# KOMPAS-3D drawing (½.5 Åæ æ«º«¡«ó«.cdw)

Views: Вид 1
Referenced files: План ПС Сазоново.cdw
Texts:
  Ирина
  Текст на чертеже
  Размерные надписи
  Шероховатость
  Линия-выноска #1
  Линия-выноска #2
  Линия-выноска #3
  Отклонения формы и база
  Заголовок таблицы
  Ячейка таблицы
  Стрелка вида
  Обозначение изменения
  Фигурная скобка
  Номер узла
  Марка координационной оси
  VRCB
  Выносная надпись
  Обозначение узла
  Марка/позиционное обозначение с линией-выноской
  Марка/позиционное обозначение на линии
  Марка/позиционное обозначение без линии-выноски
  Normal
  Лит-Масса-Масштаб
  Материал-Предприятие
  Title Specification
  Body Specification ( left align )
  Body Specificaton ( centered )
  Без имени
  heading 1
  Знак Знак Знак Знак Знак Знак
  Verdana
  Body Text
  MS Sans Serif
  Txt
  Simplex
  TXT
  Обычный
  Термин
  Список определений
  Адрес
  Цитаты
  Форматированный
  Courier New
  Z-конец формы
  Z-начало формы
  Additional DXF text style 0
  Абзац Знак
  Body Text 3
  Title
  ТекстШаг1
  Шрифт 2.5
  Заголовки
  txt
  heading 2
  AGOpus
  footer
  Денис
  RUSTXT
  Обычный (веб)
  ООббыыччнныыйй
  Definition Term
  Definition List
  Address
  Blockquote
  Preformatted
  z-Bottom of Form
  z-Top of Form
  header
  NormalParagraphStyle
  ссылки
  Подпись в квадратике
  табл
  цепи
  Маркировка
  клеммы, контакты
  тексты табл
  Тексты. 3,2
  ЗОНА_привяз
  текст переноса
  ТТееррммиинн
  ССппииссоокк ооппррееддееллеенниийй
  ААддрреесс
  ЦЦииттааттыы
  ФФооррммааттиирроовваанннныыйй
  Z-ккооннеецц ффооррммыы
  Z-ннааччааллоо ффооррммыы
  GOST 2.304 type A
  rustxt
  heading 8
  heading 3
  heading 6
  heading 7
  russ
  heading 4
  heading 5
  heading 9
  HeliosLight
  Pa3
  Pa1
  Три с половиной
  style2
  Table Contents
  Table Heading
  ГОСТ_МНЕ
  ESK - Обозначение
  маркировка
  ISOCP
  ROMANS
  SIMPLEX
  Текст 3,5
  Tahoma
  текст табл
  Пояснения 2
  romans
  gif
  ISOCPEUR
  CM12
  Клеммник текст
  Пояснения
  Ссылки
  подписи
  Аппараты
  ячейка табл.
  Состав чартежа
  CM16+18
  FR5
  Subtitle
  CNBNDG+TimesNewRoman
  Courier New Cyr
  Normal (Web)
  romanc
  eskd1
  Pa15
  Pa18
  CC С?т?и?л?ь? П?о? ц?е?н?т?р?у?
  Ошиновка
  ВЛ 110 кВ на
  ПС Ярковскую
  ПС Борки
  Примечания:
  1. Для нужд строительства (размещение задействованного в строительстве персонала, обеспечение
  электроэнергией) использовать временные мобильные инвентарные здания;
  2. При выполнении всех строительно-монтажных работ на площадке необходимо руководствоваться
  требованиями СНиП 12-03-2001 "Безопасность труда в строительстве. Общие требования",
  СНиП 12-04-2002 "Безопасность труда в строительстве. Строительное производство", а также
  ПОТ-РМ-016-2001/РД 153-34.0-03.150-00 "Межотраслевые правила по охране труда (правила
  безопасности) при эксплуатации электроустановок";
  3. Наружное освещение строительной площадки осуществляется за счет существующего освещения;
  4. Под временные сооружения (поз. II, III и IV) устраивается площадка из дорожных плит ПД 60-20 на
  щебеночном основании толщиной 15см;
  5. На период строительства для электроснабжения временных зданий и сооружений использовать ди-
  зельную электростанцию. Прокладку  кабеля от дизельной электростанции до вагончиков выполнить
  в воздушном исполнении в гофрированной трубе диаметром 30 мм, на вагончиках кабель закрепить
  скобами. Щиток временного электроснабжения навесить на стенку вагона-дома для отдыха рабочих;
  6. При выполнении монтажных работ использовать инвентарные лестницы и леса;
  7. Тонкой линией изображено существующее оборудование, замена которого проектом не предусматри-
  вается, утолщенной - вновь устанавливаемое оборудование.
  8. Условные обозначения см. 16/01-ПОС,л.1.
  9. Демонтировать ограждение на время реконструкции.
  10. Грузовысотные характеристики КМУ ИНМАН ИМ-150 см. 16/01-ПОС,л.7.
  Экспликация зданий и сооружений
  Номер
  на плане
  Постоянные здания и сооружения
  ОПУ
  Существующее
  КРУН 10 кВ
  Здание СДТУ
  Трансформатор 1Т, маслоприемник
  Существующий
  Трансформатор 2Т, маслоприемник
  Временные здания и сооружения
  III
  Вагон-дом для кратковременного отдых рабочих
  Уборная
  Дизельная электростанция
  Контейнеры для ТБО (0,75м 3 ) и жидких хоз.-быт.стоков(1м 3 )
  «Екатерина» 9,0х3,0
  Туалетная кабина "Люкс"
  ОАО ПКТИпромстрой
  см. примеч. п.9
  КМУ ИНМАН ИМ-150
  Бортовой автомобиль КамАЗ 43114-027-02
  АТ ППР#010#0104
  Перезавод ВЛ на ПС Тюмень. Реконструкция устройств
  РЗ и ПА на обратных концах отходящих ВЛ,
  ВОЛС Тюменского ТПО
  Шашерин
  Королева
  Разраб.
  Строительный генеральный план
  ПС 110/10 кВ Созоново
  ГИП
  Матвеев
  Ромин
  Общие технические условия на средний ремонт
Dimensions and other numbers on the sheet: 16/01-ПОС; 7; 2,5; 1,8; 2.5; 3,2_; 3.5; 3,2; 2,5 (контакты, клеммы); 3,2 (надписи); 3,2 (Зоны); 5; 2,5_01; 2,5_3; 3,5_01; 3,5_tabl; 5_заголовок; 2,3_; 3,2_зона не привяз; 3,5; 3.2 маркировка; 3,2 элементы; 3,2 линия; 3,2 таблица; 2,5 грязносинь; 2.5 курсив; 2.5_Э5_надписи; 2.5_Э5_ссылки; 2.5_кабель; 3.2; 2.5 надписи; 3 и 5; 5,0_белый_подчёркнутый; 3.2 фиол; 3.2 (текст); 1; 2; 3; 4; 9,6; 05.13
